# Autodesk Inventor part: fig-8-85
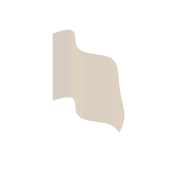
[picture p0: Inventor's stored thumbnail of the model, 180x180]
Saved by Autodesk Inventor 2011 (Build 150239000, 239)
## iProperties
Shininess: 64.0
Length Units: 11269
Angle Units: 11279
Time Units: 11290
Mass Units: 11283
Length Display Precision: 3
Angle Display Precision: 2
Compacted: True
Part Number: fig-8-85
Document SubType Name: Modeling
Created: 2003-08
Designer: Owner
Manufacturer: Standard
Standards Organization: Custom
Density: 1 g/cm^3
Density: 0.0
Volumn: 0.0
Area: 0.0
PropertySet Name: Model Information
Control State: 0
Master: False
Checked Out: False
Author: Owner
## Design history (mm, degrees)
sketch "Sketch1"
  geometry: 7 further points
  constraints: 7 other
  dimensions: "d0" = 80 horizontal distance of point (40, 1.742) point (-40, -4.065); "d1" = 40 horizontal distance of point (0, 0) point (-40, -4.065)
extrude_surface "ExtrusionSrf1" sketch "Sketch1" dims "d2" = 80, "d3" = 0
sketch "Sketch2"
  geometry: L1 (40, 0)-(40, -40) reference; L2 (-40, 0)-(-40, -40) reference; 7 further points
  constraints: 2 point on line, 7 other
extrude_surface "ExtrusionSrf2" sketch "Sketch2" dims "d4" = 80, "d5" = 0
workplane "Work Plane1"
sketch "Sketch4"
  geometry: L1 (70.027, 16.004)-(-4, 16.004); A1 r 29.004 centre (-4, -13) between (-4, 16.004) and (-2.981, -41.986)
  constraints: 2 end point, 2 point on circle, 1 centre point, 1 horizontal, 1 tangent
feature "Trim1" sketch "Sketch4"
body "Srf1"
body "Srf2"
other parameters: "d6" = -54.75
